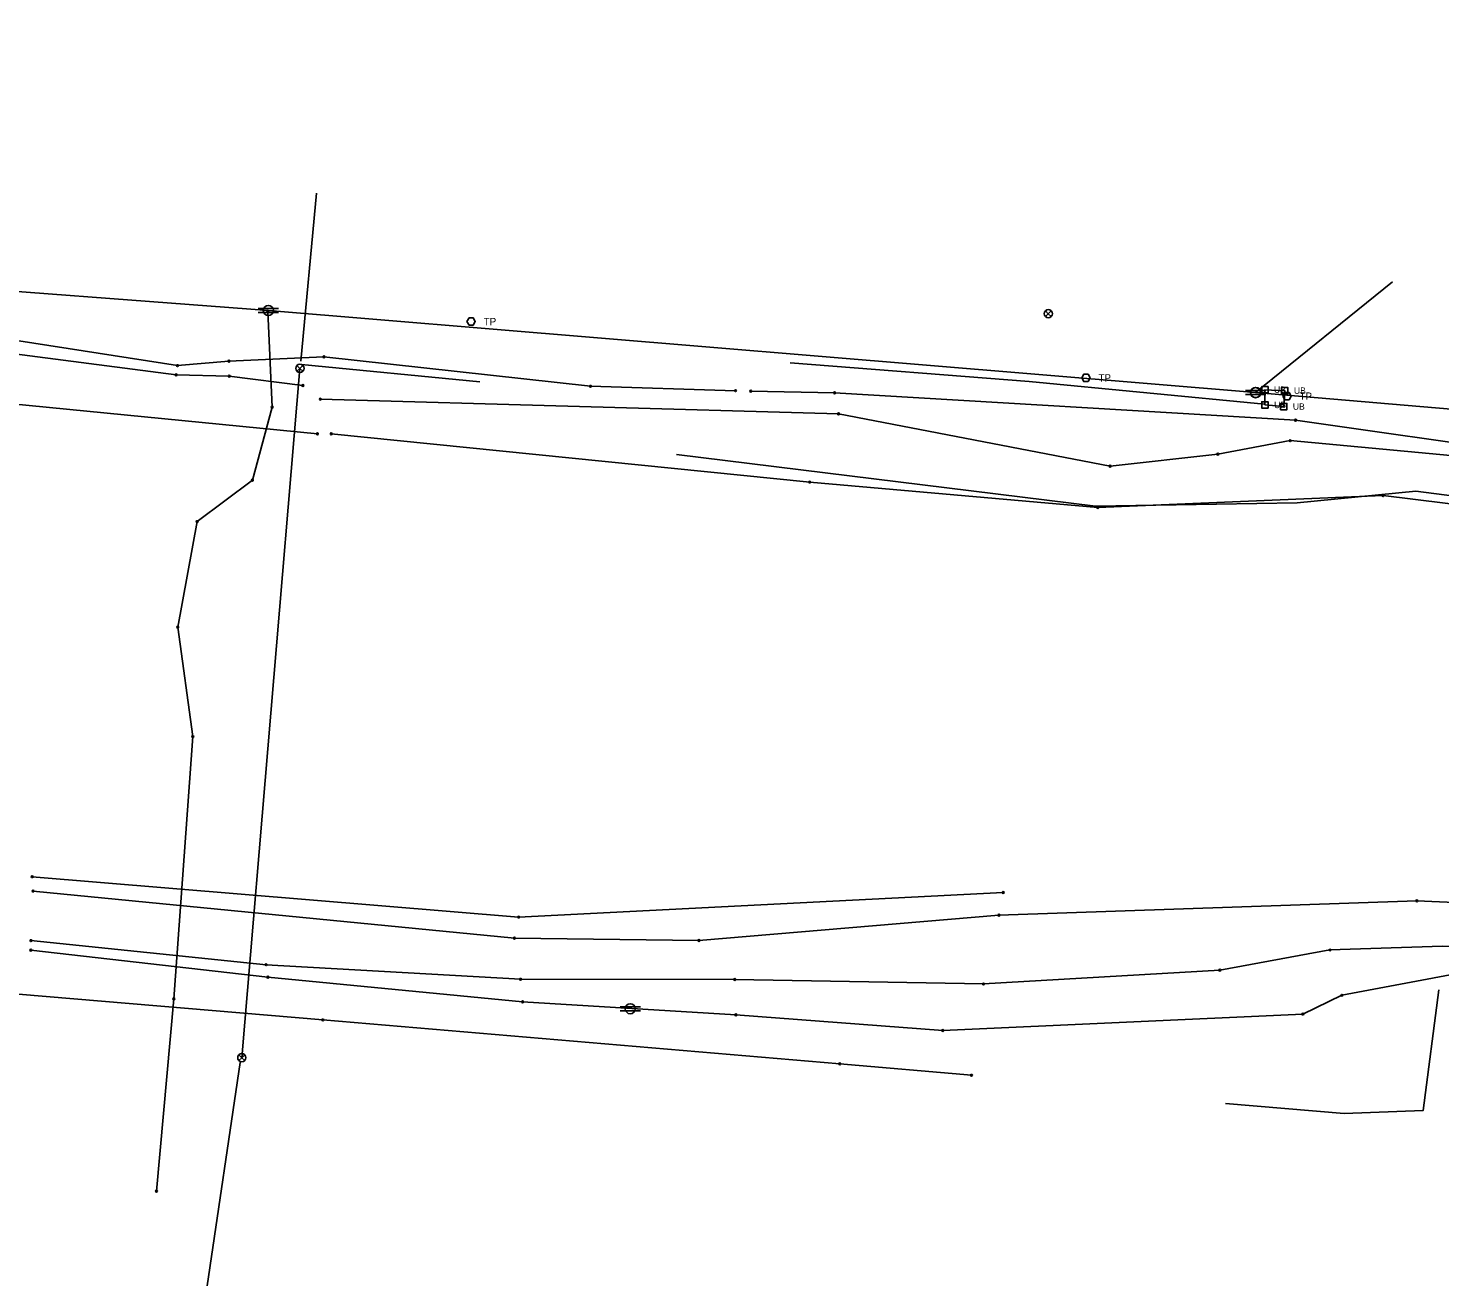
# Model space of a CAD drawing. Extents: x 20500343 to 20505311, y 7953484 to 7954193.
# Drawn here: x 20503633.2 to 20503940.9, y 7953589.4 to 7953863.5 of the extents above; entities that cross this region are included whole.
import ezdxf

# ---------------------------------------------------------------- set-up
doc = ezdxf.new("R2010")
doc.units = 0
for name, color, linetype in [('C-PROP-LINE-LOT', 7, 'Continuous'), ('V-ANNO-NOTE', 7, 'Continuous'), ('V-CTRL-HVPT', 7, 'Continuous'), ('V-MON-FND', 7, 'Continuous'), ('V-SITE-FENC', 7, 'Continuous'), ('V-SSWR-STRC', 7, 'Continuous')]:
    doc.layers.add(name, color=color, linetype=linetype)

msp = doc.modelspace()

# ---------------------------------------------------------------- linework, layer by layer
at = {"layer": 'C-PROP-LINE-LOT'}
for p, q in [((20503692.59, 7953790.91), (20503696.02, 7953827.51)), ((20503692.74, 7953790.18), (20503731.64, 7953786.45)), ((20503679.36, 7953638.08), (20503672.19, 7953589.41))]:
    msp.add_line(p, q, dxfattribs=at)
for points in [[(20502923.89, 7953863.48), (20502923.87, 7953857.22), (20502949.69, 7953853.27), (20502980.21, 7953850.33), (20503012.7, 7953848.26), (20503049, 7953845.63), (20503082.17, 7953842.1), (20503112.95, 7953839.56), (20503138.35, 7953837.73), (20503193.47, 7953832.98), (20503218.34, 7953830.79), (20503248.23, 7953827.27), (20503280.04, 7953825.39), (20503302.66, 7953821.04), (20503373.35, 7953815.08), (20503420.82, 7953809.31), (20503465.76, 7953808.12), (20503523.4, 7953802.43), (20503558.95, 7953800.72), (20503614.46, 7953794.57), (20503665.44, 7953787.94), (20503677.02, 7953787.65), (20503693.06, 7953785.61)], [(20502923.89, 7953863.47), (20502924.73, 7953858.96), (20502949.8, 7953857.13), (20502979.15, 7953855.66), (20503010.57, 7953853.39), (20503049.45, 7953848.56), (20503082.45, 7953846.12), (20503112.47, 7953843.06), (20503138.8, 7953840.76), (20503301.69, 7953823.49), (20503373.91, 7953818.29), (20503420.2, 7953815.98), (20503466.21, 7953810.37), (20503524.2, 7953805.14), (20503558.57, 7953802.46), (20503613.81, 7953798.05), (20503665.73, 7953789.96), (20503676.95, 7953790.93), (20503697.66, 7953791.85), (20503755.76, 7953785.45), (20503787.39, 7953784.49)], [(20503437.68, 7953820.69), (20503685.54, 7953801.97), (20503900.73, 7953784.06), (20504174.6, 7953760.81), (20504420.99, 7953738.08), (20504670.9, 7953722.47), (20504838.2, 7953713.61), (20505006.28, 7953702.11), (20505174.11, 7953700.54)], [(20503900.73, 7953784.06), (20503930.6, 7953808.22)], [(20503661.15, 7953610.04), (20503664.94, 7953651.94), (20503669.07, 7953709.09), (20503665.78, 7953732.95), (20503670.01, 7953755.95), (20503682.06, 7953764.98), (20503686.37, 7953780.89), (20503685.39, 7953801.83)], [(20503799.3, 7953790.53), (20503851.37, 7953786.51), (20503902.72, 7953781.57)], [(20503570.45, 7953787.4), (20503696.23, 7953775.09)], [(20503692.41, 7953789.36), (20503679.75, 7953639.12)], [(20503790.68, 7953784.4), (20503808.98, 7953784.03), (20503909.45, 7953778.06), (20503959.38, 7953770.95), (20504045.88, 7953760.22), (20504085.92, 7953755.66), (20504130.44, 7953752.67), (20504154.9, 7953748.08), (20504187.24, 7953745.87), (20504215.5, 7953745), (20504277.71, 7953741.02), (20504317.61, 7953739.57), (20504358.43, 7953733.33), (20504412.41, 7953729.48), (20504477.58, 7953724.58), (20504548.69, 7953718.7), (20504593.57, 7953715.94), (20504642.65, 7953712.07), (20504674.79, 7953710.13), (20504682, 7953710.89), (20504686.23, 7953720.21)], [(20503696.87, 7953782.64), (20503809.83, 7953779.43), (20503869.03, 7953768.03), (20503892.5, 7953770.66), (20503908.3, 7953773.6), (20503958.75, 7953768.88), (20504045.54, 7953755.47), (20504083.49, 7953748.2), (20504126.62, 7953745.29), (20504151.53, 7953743.73), (20504186.68, 7953741.39), (20504210.51, 7953740.4), (20504276.78, 7953736.15)], [(20503699.26, 7953775.1), (20503803.54, 7953764.58), (20503866.33, 7953759.03), (20503928.53, 7953761.61), (20504053.64, 7953746.16), (20504141.91, 7953734.18), (20504242.25, 7953732.31), (20504268.23, 7953730.01), (20504338.72, 7953728.07), (20504367.8, 7953726.96), (20504422.51, 7953721.81), (20504479.99, 7953718.52), (20504541.43, 7953712.4), (20504605.71, 7953707.78), (20504671.49, 7953704.84), (20504755.78, 7953700.92), (20504815.67, 7953699.69), (20504872.03, 7953696.31), (20505039.13, 7953696.21), (20505092.16, 7953700.52), (20505136.96, 7953703.53), (20505186.48, 7953709.16)], [(20503774.54, 7953770.56), (20503865.82, 7953759.32), (20503909.8, 7953760.07), (20503935.64, 7953762.61), (20504004.9, 7953753.63), (20504052.71, 7953745.8), (20504101.86, 7953738.14), (20504128.8, 7953735.15), (20504243.01, 7953731.82), (20504285.64, 7953729.43), (20504338.85, 7953727.9), (20504393.63, 7953724.94), (20504522.96, 7953714.6), (20504559.53, 7953710.68), (20504601.53, 7953709.61)], [(20502753.52, 7953725.91), (20502816.21, 7953720.99), (20502880.43, 7953715.32), (20503003.58, 7953704.35), (20503122.54, 7953695.27), (20503239.48, 7953685.69), (20503360, 7953675.01), (20503474.19, 7953666.22), (20503697.41, 7953647.35), (20503810.09, 7953637.77), (20503838.81, 7953635.29)], [(20503634.07, 7953678.56), (20503740.1, 7953669.77), (20503845.74, 7953675.11)], [(20503634.24, 7953675.44), (20503739.17, 7953665.18), (20503779.4, 7953664.67), (20503844.8, 7953670.17), (20503935.89, 7953673.31), (20504024.77, 7953669.37)], [(20503633.79, 7953664.64), (20503685.04, 7953659.39), (20503740.52, 7953656.21), (20503787.2, 7953656.16), (20503841.43, 7953655.18), (20503892.94, 7953658.2), (20503916.96, 7953662.59), (20503941.48, 7953663.41), (20503959.68, 7953662.87), (20503985.16, 7953664.06), (20504038.46, 7953659.51), (20504089.19, 7953657.06), (20504115.62, 7953651.86), (20504134.72, 7953645.31), (20504167.14, 7953633.03), (20504205.24, 7953624.66), (20504223.31, 7953619.19), (20504245.65, 7953616.64)], [(20503633.76, 7953662.54), (20503685.43, 7953656.65), (20503740.96, 7953651.29), (20503787.46, 7953648.45), (20503832.54, 7953645.05), (20503911.03, 7953648.63), (20503919.54, 7953652.71), (20503959.44, 7953660.25), (20503984.54, 7953658.4), (20504037.26, 7953655.17), (20504089.47, 7953651.11), (20504115.23, 7953650.46), (20504130.28, 7953642.23), (20504140.41, 7953634.8), (20504168.06, 7953624.18), (20504220.93, 7953608.62), (20504244.64, 7953609.51)], [(20503894.18, 7953629.16), (20503920.07, 7953626.96), (20503937.27, 7953627.58), (20503940.66, 7953653.88)]]:
    msp.add_lwpolyline(points, dxfattribs=at)
at = {"layer": 'V-ANNO-NOTE'}
for centre in [(20503685.39, 7953801.83), (20503665.73, 7953789.96), (20503676.95, 7953790.93), (20503697.66, 7953791.85), (20503665.44, 7953787.94), (20503677.02, 7953787.65), (20503693.06, 7953785.61), (20503755.76, 7953785.45), (20503787.39, 7953784.49), (20503790.68, 7953784.4), (20503808.98, 7953784.03), (20503686.37, 7953780.89), (20503696.87, 7953782.64), (20503809.83, 7953779.43), (20503909.45, 7953778.06), (20503696.23, 7953775.09), (20503699.26, 7953775.1), (20503908.3, 7953773.6), (20503869.03, 7953768.03), (20503892.5, 7953770.66), (20503682.06, 7953764.98), (20503803.54, 7953764.58), (20503866.33, 7953759.03), (20503928.53, 7953761.61), (20503670.01, 7953755.95), (20503665.78, 7953732.95), (20503669.07, 7953709.09), (20503634.07, 7953678.56), (20503634.24, 7953675.44), (20503845.74, 7953675.11), (20503935.89, 7953673.31), (20503740.1, 7953669.77), (20503844.8, 7953670.17), (20503633.79, 7953664.64), (20503739.17, 7953665.18), (20503779.4, 7953664.67), (20503633.76, 7953662.54), (20503916.96, 7953662.59), (20503685.04, 7953659.39), (20503892.94, 7953658.2), (20503685.43, 7953656.65), (20503740.52, 7953656.21), (20503787.2, 7953656.16), (20503841.43, 7953655.18), (20503664.94, 7953651.94), (20503740.96, 7953651.29), (20503919.54, 7953652.71), (20503787.46, 7953648.45), (20503911.03, 7953648.63), (20503697.41, 7953647.35), (20503832.54, 7953645.05), (20503810.09, 7953637.77), (20503838.81, 7953635.29), (20503661.15, 7953610.04)]:
    msp.add_circle(centre, 0.2, dxfattribs=at)
at = {"layer": 'V-CTRL-HVPT'}
for p, q in [((20503683.34, 7953802.42), (20503687.74, 7953802.42)), ((20503683.34, 7953801.54), (20503687.74, 7953801.54)), ((20503898.53, 7953784.51), (20503902.93, 7953784.51)), ((20503898.53, 7953783.63), (20503902.93, 7953783.63)), ((20503898.58, 7953784.54), (20503902.98, 7953784.54)), ((20503898.58, 7953783.66), (20503902.98, 7953783.66)), ((20503762.23, 7953650.23), (20503766.63, 7953650.23)), ((20503762.23, 7953649.35), (20503766.63, 7953649.35))]:
    msp.add_line(p, q, dxfattribs=at)
for centre in [(20503685.54, 7953801.97), (20503900.73, 7953784.06), (20503900.78, 7953784.1), (20503764.43, 7953649.79)]:
    msp.add_circle(centre, 1.1, dxfattribs=at)
at = {"layer": 'V-MON-FND'}
for points in [[(20503728.83, 7953799.56), (20503729.28, 7953800.35), (20503730.2, 7953800.35), (20503730.65, 7953799.56), (20503730.2, 7953798.77), (20503729.28, 7953798.77), (20503728.83, 7953799.56)], [(20503862.84, 7953787.28), (20503863.29, 7953788.07), (20503864.21, 7953788.07), (20503864.66, 7953787.28), (20503864.21, 7953786.49), (20503863.29, 7953786.49), (20503862.84, 7953787.28)], [(20503906.66, 7953783.29), (20503907.11, 7953784.09), (20503908.03, 7953784.09), (20503908.48, 7953783.29), (20503908.03, 7953782.5), (20503907.11, 7953782.5), (20503906.66, 7953783.29)]]:
    msp.add_lwpolyline(points, dxfattribs=at)
msp.add_lwpolyline([(20503902.79, 7953781.38), (20503906.87, 7953781.01), (20503907.11, 7953784.48), (20503902.76, 7953784.7)], close=True, dxfattribs=at)
msp.add_lwpolyline([(20503902.79, 7953781.38), (20503906.87, 7953781.01), (20503907.11, 7953784.48), (20503902.76, 7953784.7)], close=True, dxfattribs=at)
at = {"layer": 'V-SITE-FENC'}
for points in [[(20503902.76, 7953784.02), (20503902.76, 7953784.02), (20503903.45, 7953784.02), (20503903.45, 7953785.39), (20503902.07, 7953785.39), (20503902.07, 7953784.02), (20503902.76, 7953784.02)], [(20503907.11, 7953783.79), (20503907.11, 7953783.79), (20503907.8, 7953783.79), (20503907.8, 7953785.16), (20503906.42, 7953785.16), (20503906.42, 7953783.79), (20503907.11, 7953783.79)], [(20503902.79, 7953780.69), (20503902.79, 7953780.69), (20503903.48, 7953780.69), (20503903.48, 7953782.06), (20503902.1, 7953782.06), (20503902.1, 7953780.69), (20503902.79, 7953780.69)], [(20503906.87, 7953780.33), (20503906.87, 7953780.33), (20503907.56, 7953780.33), (20503907.56, 7953781.7), (20503906.18, 7953781.7), (20503906.18, 7953780.33), (20503906.87, 7953780.33)]]:
    msp.add_lwpolyline(points, dxfattribs=at)
at = {"layer": 'V-SSWR-STRC'}
for points in [[(20503854.92, 7953800.64), (20503855.56, 7953801.27), (20503854.92, 7953801.91)], [(20503856.2, 7953801.91), (20503855.56, 7953801.27), (20503856.2, 7953800.64)], [(20503691.77, 7953788.72), (20503692.41, 7953789.36), (20503691.77, 7953790)], [(20503693.05, 7953790), (20503692.41, 7953789.36), (20503693.05, 7953788.72)], [(20503679.11, 7953638.49), (20503679.75, 7953639.12), (20503679.11, 7953639.76)], [(20503680.39, 7953639.76), (20503679.75, 7953639.12), (20503680.39, 7953638.49)]]:
    msp.add_lwpolyline(points, dxfattribs=at)
for centre, start, end in [((20503855.56, 7953801.27), 135, 225), ((20503855.56, 7953801.27), 45, 135), ((20503855.56, 7953801.27), 315, 45), ((20503855.56, 7953801.27), 225, 315), ((20503692.41, 7953789.36), 135, 225), ((20503692.41, 7953789.36), 45, 135), ((20503692.41, 7953789.36), 315, 45), ((20503692.41, 7953789.36), 225, 315), ((20503679.75, 7953639.12), 135, 225), ((20503679.75, 7953639.12), 45, 135), ((20503679.75, 7953639.12), 315, 45), ((20503679.75, 7953639.12), 225, 315)]:
    msp.add_arc(centre, 0.899, start, end, dxfattribs=at)

# ---------------------------------------------------------------- texts
at = {"layer": 'V-MON-FND'}
for p in [(20503732.48, 7953798.76), (20503866.49, 7953786.48), (20503910.31, 7953782.5)]:
    msp.add_text('TP', height=1.599, dxfattribs=at).set_placement(p)
at = {"layer": 'V-SITE-FENC'}
for p in [(20503904.75, 7953784.02), (20503909.1, 7953783.8), (20503904.78, 7953780.69), (20503908.86, 7953780.33)]:
    msp.add_text('UB', height=1.399, dxfattribs=at).set_placement(p)

doc.saveas('drawing.dxf')
